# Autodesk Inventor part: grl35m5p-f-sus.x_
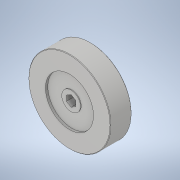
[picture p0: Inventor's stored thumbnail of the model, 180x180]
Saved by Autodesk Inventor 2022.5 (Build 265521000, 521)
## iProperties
Created: 2021-02
Part Number: grl35m5p-f-sus.x_
Material: 一般
Document SubType Name: Modeling
Designer: ImaoCorp
Density: 1 g/cm^3
Appearance: 既定
Sending System: SOLIDWORKS 2019-2019304
MC: AMD64
MC_MODEL: Intel64 Family 6 Model 60 Stepping 3, GenuineIntel
OS: Windows_NT
FRU: Parasolid Version 31.0, build 290,  9- 1-2019
FORMAT: text
GUISE: transmit
KEY: grl35m5p-f-sus
FILE: grl35m5p-f-sus.x_t
DATE: Mon Feb 22 15:02:20 2021
Author: ImaoCorp
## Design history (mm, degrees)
feature "Base1"
node "ソリッド1"
